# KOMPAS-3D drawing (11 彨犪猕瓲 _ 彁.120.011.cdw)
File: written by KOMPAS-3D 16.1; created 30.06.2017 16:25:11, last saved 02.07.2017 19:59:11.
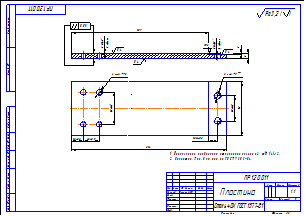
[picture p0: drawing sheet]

Sheet 1: A3, landscape

Title block, sheet 1: name: Пластина; designation: ПР.120.011; material: Сталь 40Х ГОСТ 1577-81; scale: 1:1; sheets: 1; sheet format: A3; stored path: D:\VSE\Эрга\Оснастка\Гибка лепестков\Прохвост\Пластина _ К17.479.011.cdw; drawn by: Сигачев СИ

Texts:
  Sergey
  Неуказанные предельные отклонения размеров   (IT 14)/2.
  Покрытие: Хим. Окс. прм по ГОСТ 9.303-84.
  Ra3,2
  Ra3,2 ( )
Dimensions and other numbers on the sheet: 0,4; 0,05; 0,5; 8 фасок; 2; 8; 4 фаски; 0,3; 4 отв.; 7,5; 45±0,1; 2 отв.; 9; 35±0,1; 75; 12,5±0,2; 16±0,2; 22±0,1; 214; 189; 1:1; 1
